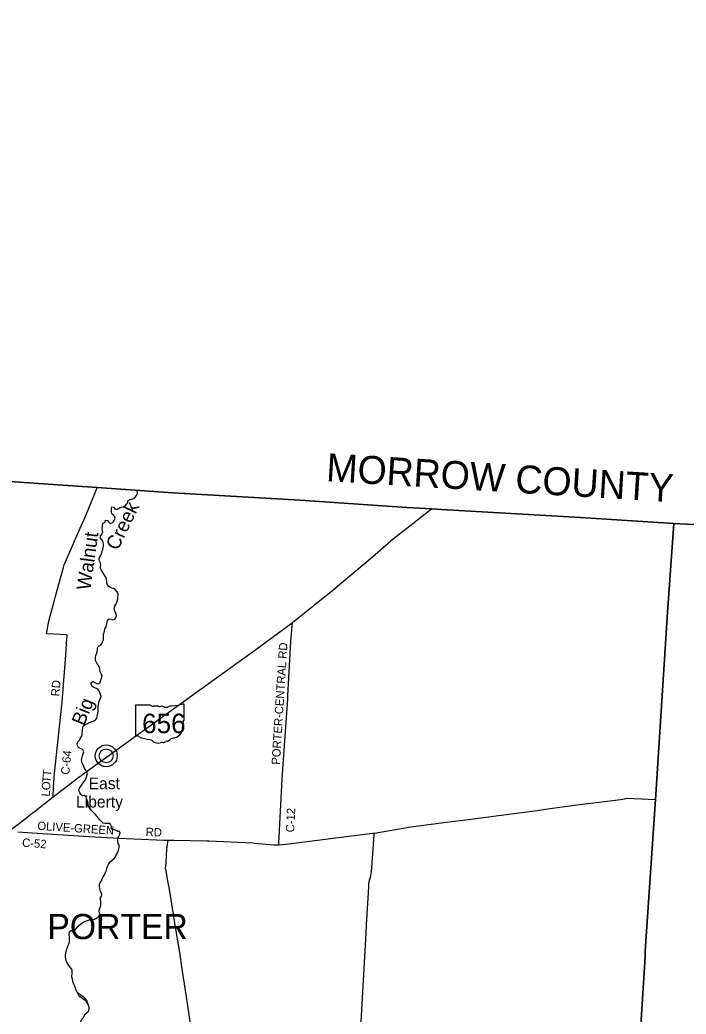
# Model space of a CAD drawing. Extents: x 1674899 to 2057726, y 653888 to 988278.
# Drawn here: x 1876887 to 1900667, y 838394 to 873883 of the extents above; entities that cross this region are included whole.
import ezdxf

# ---------------------------------------------------------------- set-up
doc = ezdxf.new("R2010")
doc.units = 0
for name, color, linetype in [('GM_X_Adjacent_County', 7, 'Continuous'), ('GM_X_Adjacent_County_Text', 7, 'Continuous'), ('GM_X_County', 7, 'Continuous'), ('GM_X_County_Road', 7, 'Continuous'), ('GM_X_County_Road_Text', 7, 'Continuous'), ('GM_X_Major_River', 7, 'Continuous'), ('GM_X_Major_River_Text', 7, 'Continuous'), ('GM_X_State_Location', 7, 'Continuous'), ('GM_X_State_Route', 7, 'Continuous'), ('GM_X_State_Shield', 7, 'Continuous'), ('GM_X_Township', 7, 'Continuous'), ('GM_X_Township_Text', 7, 'Continuous'), ('GM_X_Unincorporated', 7, 'Continuous'), ('GM_X_Unincorporated_Location', 7, 'Continuous'), ('GM_X_Unincorporated_Text', 7, 'Continuous')]:
    doc.layers.add(name, color=color, linetype=linetype)

msp = doc.modelspace()

# ---------------------------------------------------------------- linework, layer by layer
at = {"layer": 'GM_X_Adjacent_County'}
for points in [[(1898887, 835373), (1899202, 840435), (1899208, 840537), (1899210, 840637), (1899571, 846055), (1900008, 852727), (1900228, 855908), (1900447, 855895), (1900992, 855867), (1905546, 855583), (1909640, 855342), (1915609, 854967), (1916549, 854893), (1922111, 854537), (1924873, 854361), (1927658, 854184), (1927777, 856135), (1927907, 858279), (1927988, 859624), (1928189, 862861), (1928314, 865105), (1928341, 865325), (1928849, 873883)], [(1900992, 855867), (1900447, 855895), (1900228, 855908), (1896895, 856116), (1891937, 856405), (1891588, 856432), (1890695, 856480), (1886895, 856734), (1882352, 856998), (1879641, 857188), (1876143, 857428), (1873671, 857558), (1869100, 857855), (1863977, 858188), (1861827, 858324), (1850615, 859080)]]:
    msp.add_lwpolyline(points, dxfattribs=at)
at = {"layer": 'GM_X_County'}
msp.add_lwpolyline([(1850615, 859080), (1861827, 858324), (1863977, 858188), (1869100, 857855), (1873671, 857558), (1876143, 857428), (1879641, 857188), (1882352, 856998), (1886895, 856734), (1890695, 856480), (1891588, 856432), (1891937, 856405), (1896895, 856116), (1900228, 855908), (1900008, 852727), (1899571, 846055), (1899210, 840637), (1899208, 840537), (1899202, 840435), (1898887, 835373)], dxfattribs=at)
at = {"layer": 'GM_X_County_Road'}
for points in [[(1878069, 846144), (1878085, 846512), (1878125, 846983), (1878226, 847978), (1878395, 849532), (1878536, 851373), (1878554, 851651), (1878570, 851880), (1878570, 851906), (1878562, 851922), (1878551, 851936), (1878115, 851952), (1877831, 851971), (1877925, 852422), (1878131, 853220), (1878152, 853318), (1878443, 854333), (1878470, 854429), (1879125, 855929), (1879153, 855993), (1879536, 856921), (1879568, 856998), (1879605, 857097), (1879641, 857189)], [(1886129, 844439), (1886132, 844491), (1886249, 846785), (1886257, 846969), (1886270, 847136), (1886449, 849651), (1886451, 849675), (1886456, 849754), (1886558, 851700), (1886613, 852377)], [(1876809, 844899), (1877320, 844863), (1879351, 844730), (1880430, 844669), (1882026, 844608), (1882181, 844601), (1882392, 844602), (1883554, 844583), (1883632, 844581), (1885215, 844502), (1885270, 844499), (1885954, 844440), (1886129, 844439), (1886387, 844458), (1889478, 844848), (1889539, 844855), (1890840, 845073), (1892109, 845243), (1892893, 845346), (1894066, 845501), (1894790, 845594), (1895349, 845664), (1895569, 845695), (1895814, 845736), (1896247, 845793), (1896967, 845887), (1898141, 846028), (1898411, 846062), (1898560, 846100), (1898798, 846088), (1899571, 846055)], [(1888604, 829939), (1888609, 830001), (1888760, 832637), (1888800, 833137), (1888812, 833505), (1889049, 837835), (1889053, 837918), (1889133, 839176), (1889247, 841285), (1889264, 841582), (1889332, 842735), (1889339, 842955), (1889347, 843044), (1889371, 843177), (1889414, 843329), (1889428, 843400), (1889436, 843472), (1889534, 844778), (1889539, 844855)], [(1883352, 835653), (1883345, 835749), (1883225, 836391), (1883075, 837371), (1882925, 838372), (1882793, 839248), (1882676, 839999), (1882590, 840590), (1882528, 840993), (1882422, 841658), (1882235, 842776), (1882147, 843282), (1882115, 843443), (1882081, 843608), (1882104, 843778), (1882120, 844088), (1882142, 844371), (1882181, 844601)]]:
    msp.add_lwpolyline(points, dxfattribs=at)
at = {"layer": 'GM_X_Major_River'}
for points in [[(1880386, 853271), (1880392, 853325), (1880393, 853403), (1880365, 853463), (1880295, 853536), (1880234, 853582), (1880172, 853600), (1880120, 853625), (1880056, 853663), (1880012, 853721), (1879993, 853794), (1879993, 853846), (1879977, 853912), (1879952, 853988), (1879912, 854060), (1879869, 854123), (1879791, 854253), (1879766, 854305), (1879766, 854369), (1879776, 854433), (1879761, 854496), (1879725, 854564), (1879711, 854628), (1879728, 854694), (1879760, 854748), (1879789, 854802), (1879815, 854874), (1879823, 854928), (1879846, 854984), (1879858, 855042), (1879866, 855112), (1879869, 855170), (1879865, 855220), (1879843, 855270), (1879812, 855320), (1879766, 855387), (1879768, 855461), (1879807, 855521), (1879845, 855593), (1879838, 855659), (1879828, 855723), (1879830, 855787), (1879831, 855849), (1879853, 855913), (1879917, 855945), (1879944, 856021), (1880012, 856018), (1880065, 855952), (1880127, 855906), (1880183, 855933), (1880238, 855987), (1880278, 856049), (1880287, 856119), (1880237, 856189), (1880169, 856254), (1880154, 856306), (1880152, 856384), (1880160, 856446), (1880171, 856498), (1880233, 856490), (1880274, 856426), (1880340, 856403), (1880403, 856447), (1880467, 856479), (1880519, 856494), (1880581, 856504), (1880641, 856540), (1880692, 856594), (1880742, 856639), (1880744, 856716), (1880815, 856765), (1880877, 856771), (1880941, 856793), (1880993, 856840), (1881053, 856902), (1881080, 856972), (1881077, 857076)], [(1879139, 847824), (1879109, 847850), (1879048, 847879), (1878980, 847905), (1878938, 847979), (1878933, 848045), (1878951, 848117), (1879021, 848179), (1879056, 848251), (1879092, 848311), (1879107, 848379), (1879111, 848433), (1879117, 848483), (1879127, 848537), (1879138, 848607), (1879150, 848673), (1879213, 848729), (1879277, 848751), (1879339, 848786), (1879405, 848818), (1879457, 848836), (1879530, 848863), (1879580, 848897), (1879632, 848959), (1879647, 849031), (1879655, 849081), (1879669, 849139), (1879676, 849213), (1879680, 849265), (1879680, 849325), (1879681, 849387), (1879687, 849437), (1879699, 849507), (1879722, 849567), (1879742, 849621), (1879772, 849679), (1879783, 849743), (1879767, 849805), (1879746, 849870), (1879712, 849932), (1879656, 850000), (1879590, 850033), (1879519, 850059), (1879453, 850097), (1879433, 850166), (1879436, 850234), (1879494, 850268), (1879566, 850231), (1879631, 850193), (1879687, 850184), (1879740, 850210), (1879766, 850278), (1879786, 850344), (1879809, 850418), (1879821, 850478), (1879783, 850544), (1879750, 850613), (1879736, 850685), (1879733, 850749), (1879703, 850821), (1879657, 850877), (1879618, 850940), (1879582, 851012), (1879580, 851070), (1879589, 851126), (1879603, 851192), (1879620, 851256), (1879644, 851328), (1879654, 851394), (1879659, 851444), (1879671, 851498), (1879721, 851536), (1879771, 851558), (1879812, 851620), (1879834, 851684), (1879867, 851752), (1879867, 851878), (1879870, 851952), (1879892, 852012), (1879905, 852076), (1879921, 852144), (1879969, 852214), (1879980, 852280), (1880000, 852380), (1880019, 852456), (1880075, 852505), (1880139, 852493), (1880201, 852469), (1880265, 852474), (1880313, 852536), (1880334, 852608), (1880318, 852678), (1880293, 852743), (1880259, 852817), (1880251, 852885), (1880278, 852961), (1880306, 853013), (1880339, 853065), (1880365, 853129), (1880381, 853209), (1880386, 853271)], [(1880465, 844879), (1880431, 844929), (1880381, 844916), (1880323, 844950), (1880253, 844970), (1880203, 844971), (1880162, 845035), (1880152, 845087), (1880126, 845161), (1880075, 845194), (1880011, 845196), (1879945, 845192), (1879865, 845215), (1879801, 845265), (1879741, 845330), (1879690, 845394), (1879630, 845458), (1879580, 845519), (1879521, 845579), (1879459, 845647), (1879405, 845710), (1879354, 845778), (1879324, 845842), (1879318, 845919), (1879309, 845969), (1879285, 846029), (1879275, 846083), (1879240, 846149), (1879188, 846194), (1879124, 846184), (1879070, 846230), (1879030, 846297), (1879005, 846347), (1878995, 846401), (1879030, 846475), (1879080, 846539), (1879126, 846610), (1879175, 846684), (1879213, 846746), (1879248, 846816), (1879278, 846898), (1879298, 846966), (1879273, 847032), (1879237, 847099), (1879198, 847163), (1879172, 847227), (1879140, 847293), (1879113, 847364), (1879097, 847414), (1879089, 847464), (1879096, 847514), (1879106, 847564), (1879122, 847616), (1879147, 847690), (1879165, 847756), (1879139, 847824)], [(1878926, 839165), (1878906, 839215), (1878888, 839269), (1878873, 839322), (1878849, 839390), (1878813, 839458), (1878794, 839522), (1878778, 839574), (1878760, 839641), (1878741, 839707), (1878737, 839761), (1878748, 839827), (1878754, 839879), (1878756, 839935), (1878735, 840001), (1878679, 840068), (1878629, 840134), (1878604, 840188), (1878560, 840250), (1878532, 840317), (1878521, 840369), (1878515, 840425), (1878515, 840505), (1878526, 840571), (1878538, 840631), (1878550, 840685), (1878569, 840741), (1878587, 840795), (1878613, 840849), (1878640, 840921), (1878654, 840979), (1878656, 841041), (1878657, 841091), (1878655, 841145), (1878651, 841209), (1878648, 841269), (1878658, 841336), (1878718, 841377), (1878786, 841383), (1878857, 841407), (1878917, 841476), (1878971, 841536), (1879040, 841598), (1879106, 841652), (1879178, 841687), (1879228, 841709), (1879297, 841741), (1879367, 841762), (1879429, 841762), (1879481, 841766), (1879545, 841780), (1879603, 841811), (1879667, 841849), (1879718, 841905), (1879738, 841975), (1879711, 842047), (1879711, 842099), (1879743, 842165), (1879770, 842237), (1879774, 842287), (1879780, 842341), (1879777, 842415), (1879767, 842483), (1879763, 842548), (1879794, 842599), (1879808, 842665), (1879791, 842738), (1879757, 842810), (1879737, 842878), (1879728, 842950), (1879730, 843016), (1879738, 843068), (1879795, 843148), (1879825, 843220), (1879852, 843272), (1879884, 843324), (1879914, 843390), (1879941, 843462), (1879973, 843528), (1879993, 843588), (1880016, 843658), (1880036, 843710), (1880056, 843766), (1880113, 843832), (1880177, 843887), (1880246, 843939), (1880298, 844009), (1880318, 844065), (1880359, 844129), (1880385, 844185), (1880403, 844247), (1880416, 844299), (1880426, 844349), (1880430, 844421), (1880399, 844489), (1880379, 844557), (1880379, 844609), (1880386, 844663), (1880416, 844741), (1880453, 844813), (1880465, 844879)], [(1878926, 839165), (1878985, 839043), (1879045, 839008), (1879115, 838972), (1879181, 838921), (1879236, 838857), (1879274, 838793), (1879312, 838771)], [(1879312, 838771), (1879300, 838809), (1879282, 838879), (1879233, 838943), (1879173, 838994), (1879107, 839038), (1879037, 839086), (1878926, 839165)], [(1878726, 837866), (1878738, 837858), (1878804, 837802), (1878866, 837795), (1878932, 837815), (1878992, 837867), (1879019, 837935), (1879037, 838007), (1879050, 838081), (1879072, 838149), (1879115, 838221), (1879163, 838275), (1879181, 838329), (1879212, 838399), (1879278, 838448), (1879340, 838498), (1879355, 838568), (1879355, 838634), (1879337, 838700), (1879312, 838771)]]:
    msp.add_lwpolyline(points, dxfattribs=at)
at = {"layer": 'GM_X_State_Route'}
for points in [[(1877908, 846019), (1878069, 846144), (1878991, 846854), (1880073, 847637), (1885437, 851504), (1886613, 852377), (1888074, 853536), (1889468, 854711), (1890217, 855366), (1890913, 855912), (1891583, 856425)], [(1875906, 844320), (1876154, 844572), (1876386, 844812), (1876497, 844924), (1876868, 845210), (1877089, 845378), (1877250, 845505), (1877281, 845529), (1877348, 845583), (1877908, 846019)]]:
    msp.add_lwpolyline(points, dxfattribs=at)
at = {"layer": 'GM_X_State_Shield'}
for p, q in [((1881008, 849405), (1881008, 848349)), ((1881535, 849423), (1881025, 849423)), ((1882748, 848897), (1882748, 849450)), ((1882748, 848897), (1882748, 848897))]:
    msp.add_line(p, q, dxfattribs=at)
for centre, major_axis, start_param, end_param in [((1881028, 849408), (20.2, 0), 1.712693, 3.28349), ((1881656, 849546), (196, 0), 4.042523, 4.731795), ((1881721, 848830), (702, 0), 1.404758, 1.657858), ((1881880, 849413), (56.4, 0), 3.836095, 5.185415), ((1881963, 849291), (117, 0), 0.950623, 2.079405), ((1882114, 849458), (141, 0), 4.081561, 5.145723), ((1882364, 849101), (371, 0), 1.699011, 2.107814), ((1882128, 850864), (1845, 0), 4.814394, 5.042369), ((1882729, 849452), (19.4, 0), 6.141152, 7.989035), ((1882727, 848895), (20.7, 0), 5.05454, 6.418171), ((1882232, 848595), (462, 0), 5.101752, 6.440018), ((1882818, 848666), (131, 0), 2.387724, 3.262537), ((1882744, 848856), (30, 0), 1.883978, 3.671073), ((1882553, 848786), (180, 0), 5.934695, 6.695948), ((1881028, 848346), (20.3, 0), 3.00124, 4.508301), ((1881031, 848454), (155, 0), 4.665946, 4.897461), ((1881063, 848288), (56, 0), 0.519207, 1.627899), ((1881769, 849237), (1333, 0), 4.195997, 4.488961), ((1881372, 847874), (417, 0), 0.823519, 1.323587), ((1882426, 848052), (253, 0), 1.647645, 2.488434), ((1881823, 848282), (265, 0), 4.026481, 4.996735), ((1881976, 847917), (217, 0), 1.495662, 1.94098), ((1881995, 848203), (141, 0), 4.691044, 5.507374), ((1882123, 848101), (39.7, 0), 1.147584, 2.315152), ((1882106, 848246), (149, 0), 4.937069, 5.64225)]:
    msp.add_ellipse(centre, major_axis=major_axis, ratio=0.8, start_param=start_param, end_param=end_param, dxfattribs=at)
at = {"layer": 'GM_X_Township'}
msp.add_lwpolyline([(1872306, 836385), (1872497, 839344), (1872678, 842151), (1872874, 845201), (1872889, 845433), (1873266, 851105), (1873447, 853777), (1873671, 857558), (1876143, 857428), (1879641, 857188), (1882352, 856998), (1886895, 856734), (1890695, 856480), (1891588, 856432), (1891937, 856405), (1896895, 856116), (1900228, 855908), (1900008, 852727), (1899571, 846055), (1899210, 840637), (1899208, 840537), (1899202, 840435), (1898887, 835373)], dxfattribs=at)
at = {"layer": 'GM_X_Unincorporated'}
for radius in [393, 249]:
    msp.add_circle((1879968, 847613), radius, dxfattribs=at)
at = {"layer": 'GM_X_Unincorporated_Location'}
msp.add_line((1879968, 847613), (1879968, 847613), dxfattribs=at)

# ---------------------------------------------------------------- texts
at = {"layer": 'GM_X_Adjacent_County_Text'}
msp.add_text('MORROW COUNTY', height=1000, rotation=356.5133, dxfattribs=at).set_placement((1887802, 857418))
at = {"layer": 'GM_X_County_Road_Text'}
for s, rotation, p in [('PORTER-CENTRAL RD', 86.3782, (1886166, 847289)), ('RD', 85.5238, (1878295, 849727)), ('C-64', 84.1868, (1878645, 846928)), ('T', 84.3337, (1877998, 846865)), ('T', 85.2246, (1877979, 846643)), ('O', 86.6248, (1877964, 846381)), ('L', 87.788, (1877955, 846158)), ('C-12', 87.2576, (1886677, 844875)), ('OLIVE-GREEN', 356.3018, (1877501, 844974)), ('RD', 357.5314, (1881370, 844754)), ('C-52', 355.8642, (1876958, 844372))]:
    msp.add_text(s, height=300, rotation=rotation, dxfattribs=at).set_placement(p)
at = {"layer": 'GM_X_Major_River_Text'}
for s, height, rotation, p in [('Creek', 500.1, 64.044, (1880378, 854914)), ('Walnut', 500, 81.8901, (1879399, 853505)), ('Big', 500, 68.2241, (1879179, 848658))]:
    msp.add_text(s, height=height, rotation=rotation, dxfattribs=at).set_placement(p)
at = {"layer": 'GM_X_State_Location'}
msp.add_text('656', height=1, rotation=0, dxfattribs=at).set_placement((1881505, 848734))
for s in ['s', 'r']:
    msp.add_text(s, height=1, dxfattribs=at).set_placement((1881858, 848807))
at = {"layer": 'GM_X_State_Shield'}
msp.add_text('656', height=696.1, dxfattribs=at).set_placement((1881250, 848423))
at = {"layer": 'GM_X_Township_Text'}
msp.add_text('PORTER', height=900, rotation=0, dxfattribs=at).set_placement((1877867, 841070))
at = {"layer": 'GM_X_Unincorporated_Text'}
for s, p in [('East', (1879341, 846422)), ('Liberty', (1878892, 845767))]:
    msp.add_text(s, height=417, rotation=0, dxfattribs=at).set_placement(p)

doc.saveas('drawing.dxf')
